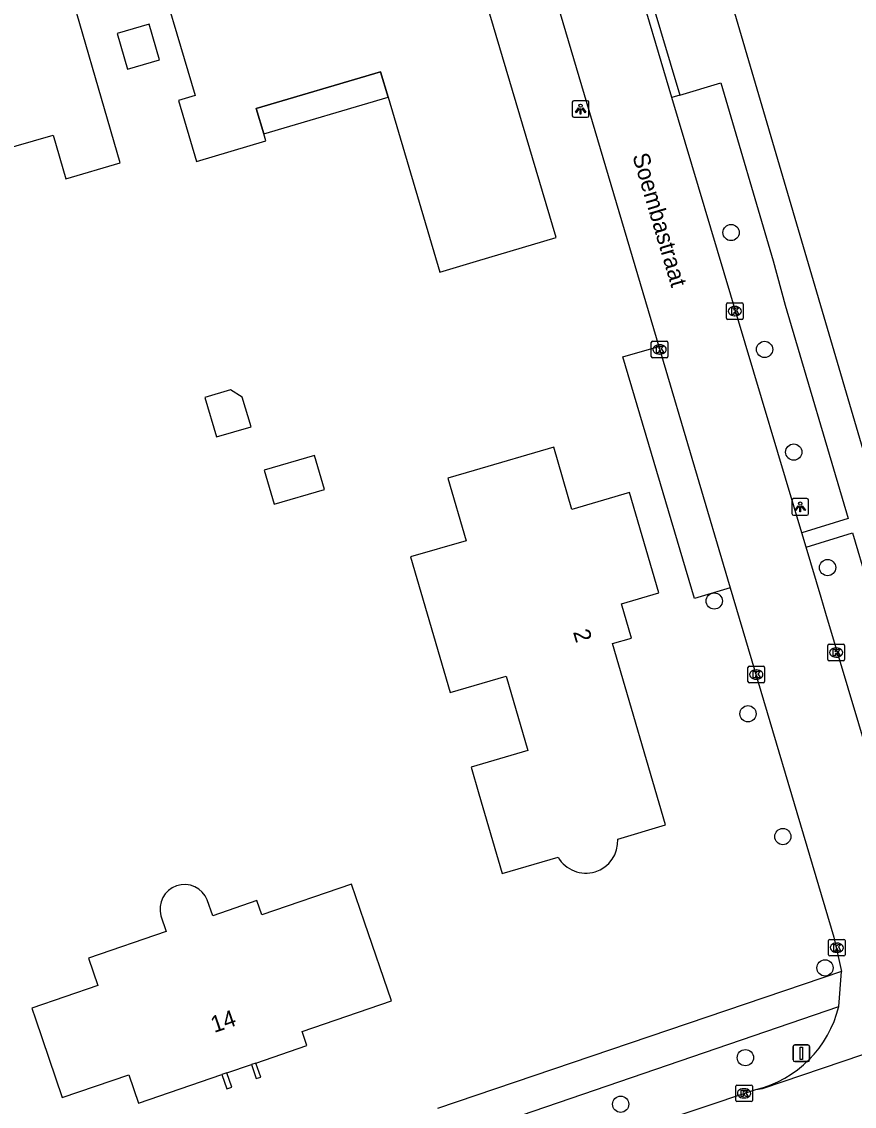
# Model space of a CAD drawing. Extents: x 162417 to 163721, y 384268 to 385416.
# Drawn here: x 163274.6 to 163324.7, y 384590.7 to 384656 of the extents above; entities that cross this region are included whole.
import ezdxf

# ---------------------------------------------------------------- set-up
doc = ezdxf.new("R2010")
doc.units = 0
for name, color, linetype in [('IMGEO_Boom', 7, 'Continuous'), ('IMGEO_Kolk', 7, 'Continuous'), ('IMGEO_Lichtpunt', 7, 'Continuous'), ('IMGEO_Muur', 7, 'Continuous'), ('IMGEO_Openbare_ruimte_label', 7, 'Continuous'), ('IMGEO_Pand', 7, 'Continuous'), ('IMGEO_Pand_nummerreeks', 7, 'Continuous'), ('IMGEO_Pand_overbouw', 7, 'Continuous'), ('IMGEO_Rijbaan_lokaal_open', 7, 'Continuous'), ('IMGEO_Verkeersbordpaal', 7, 'Continuous'), ('IMGEO_Voetpad_open', 7, 'Continuous')]:
    doc.layers.add(name, color=color, linetype=linetype)

msp = doc.modelspace()

# ---------------------------------------------------------------- linework, layer by layer
at = {"layer": 'IMGEO_Boom'}
for centre in [(163317.284, 384643.273), (163319.297, 384636.239), (163321.054, 384630.059), (163323.09, 384623.109), (163316.269, 384621.1), (163318.299, 384614.313), (163320.398, 384606.923), (163322.938, 384599.019), (163318.144, 384593.615), (163310.637, 384590.813)]:
    msp.add_circle(centre, 0.489, dxfattribs=at)
at = {"layer": 'IMGEO_Kolk'}
for p, q in [((163317.082, 384639.043), (163317.934, 384639.043)), ((163317.007, 384638.117), (163317.007, 384638.969)), ((163317.495, 384638.823), (163317.52, 384638.823)), ((163318.008, 384638.969), (163318.008, 384638.117)), ((163317.934, 384638.043), (163317.082, 384638.043)), ((163317.518, 384638.263), (163317.493, 384638.263)), ((163312.48, 384635.812), (163312.48, 384636.664)), ((163312.555, 384636.738), (163313.407, 384636.738)), ((163312.968, 384636.518), (163312.993, 384636.518)), ((163313.481, 384636.664), (163313.481, 384635.812)), ((163312.991, 384635.958), (163312.966, 384635.958)), ((163313.407, 384635.738), (163312.555, 384635.738)), ((163323.107, 384617.572), (163323.107, 384618.424)), ((163323.182, 384618.498), (163324.034, 384618.498)), ((163323.595, 384618.278), (163323.62, 384618.278)), ((163324.108, 384618.424), (163324.108, 384617.572)), ((163323.618, 384617.718), (163323.593, 384617.718)), ((163318.298, 384616.244), (163318.298, 384617.096)), ((163318.373, 384617.17), (163319.225, 384617.17)), ((163318.786, 384616.95), (163318.811, 384616.95)), ((163319.299, 384617.096), (163319.299, 384616.244)), ((163324.034, 384617.498), (163323.182, 384617.498)), ((163318.809, 384616.39), (163318.784, 384616.39)), ((163319.225, 384616.17), (163318.373, 384616.17)), ((163323.148, 384599.809), (163323.148, 384600.661)), ((163323.223, 384600.735), (163324.075, 384600.735)), ((163324.149, 384600.661), (163324.149, 384599.809)), ((163323.659, 384599.955), (163323.634, 384599.955)), ((163323.636, 384600.515), (163323.661, 384600.515)), ((163324.075, 384599.735), (163323.223, 384599.735)), ((163317.563, 384591.043), (163317.563, 384591.895)), ((163317.638, 384591.969), (163318.49, 384591.969)), ((163318.051, 384591.749), (163318.076, 384591.749)), ((163318.564, 384591.895), (163318.564, 384591.043)), ((163318.49, 384590.969), (163317.638, 384590.969)), ((163318.074, 384591.189), (163318.049, 384591.189))]:
    msp.add_line(p, q, dxfattribs=at)
for points in [[(163317.082, 384639.043), (163317.934, 384639.043)], [(163317.007, 384638.117), (163317.007, 384638.969)], [(163317.328, 384638.743), (163317.451, 384638.743), (163317.451, 384638.592), (163317.581, 384638.743), (163317.745, 384638.743), (163317.599, 384638.592), (163317.752, 384638.343), (163317.6, 384638.343), (163317.515, 384638.507), (163317.451, 384638.44), (163317.451, 384638.343), (163317.328, 384638.343), (163317.328, 384638.743)], [(163318.008, 384638.969), (163318.008, 384638.117)], [(163317.934, 384638.043), (163317.082, 384638.043)], [(163312.48, 384635.812), (163312.48, 384636.664)], [(163312.555, 384636.738), (163313.407, 384636.738)], [(163312.801, 384636.438), (163312.924, 384636.438), (163312.924, 384636.287), (163313.054, 384636.438), (163313.218, 384636.438), (163313.072, 384636.287), (163313.225, 384636.038), (163313.073, 384636.038), (163312.988, 384636.202), (163312.924, 384636.135), (163312.924, 384636.038), (163312.801, 384636.038), (163312.801, 384636.438)], [(163313.481, 384636.664), (163313.481, 384635.812)], [(163313.407, 384635.738), (163312.555, 384635.738)], [(163323.107, 384617.572), (163323.107, 384618.424)], [(163323.182, 384618.498), (163324.034, 384618.498)], [(163323.428, 384618.198), (163323.551, 384618.198), (163323.551, 384618.047), (163323.681, 384618.198), (163323.845, 384618.198), (163323.699, 384618.047), (163323.852, 384617.798), (163323.7, 384617.798), (163323.615, 384617.962), (163323.551, 384617.895), (163323.551, 384617.798), (163323.428, 384617.798), (163323.428, 384618.198)], [(163324.108, 384618.424), (163324.108, 384617.572)], [(163318.298, 384616.244), (163318.298, 384617.096)], [(163318.373, 384617.17), (163319.225, 384617.17)], [(163318.619, 384616.87), (163318.742, 384616.87), (163318.742, 384616.719), (163318.872, 384616.87), (163319.036, 384616.87), (163318.89, 384616.719), (163319.043, 384616.47), (163318.891, 384616.47), (163318.806, 384616.634), (163318.742, 384616.567), (163318.742, 384616.47), (163318.619, 384616.47), (163318.619, 384616.87)], [(163319.299, 384617.096), (163319.299, 384616.244)], [(163324.034, 384617.498), (163323.182, 384617.498)], [(163319.225, 384616.17), (163318.373, 384616.17)], [(163323.148, 384599.809), (163323.148, 384600.661)], [(163323.223, 384600.735), (163324.075, 384600.735)], [(163324.149, 384600.661), (163324.149, 384599.809)], [(163323.469, 384600.435), (163323.592, 384600.435), (163323.592, 384600.284), (163323.722, 384600.435), (163323.886, 384600.435), (163323.74, 384600.284), (163323.893, 384600.035), (163323.741, 384600.035), (163323.656, 384600.199), (163323.592, 384600.132), (163323.592, 384600.035), (163323.469, 384600.035), (163323.469, 384600.435)], [(163324.075, 384599.735), (163323.223, 384599.735)], [(163317.563, 384591.043), (163317.563, 384591.895)], [(163317.638, 384591.969), (163318.49, 384591.969)], [(163317.884, 384591.669), (163318.007, 384591.669), (163318.007, 384591.518), (163318.137, 384591.669), (163318.301, 384591.669), (163318.155, 384591.518), (163318.308, 384591.269), (163318.156, 384591.269), (163318.071, 384591.433), (163318.007, 384591.366), (163318.007, 384591.269), (163317.884, 384591.269), (163317.884, 384591.669)], [(163318.564, 384591.895), (163318.564, 384591.043)], [(163318.49, 384590.969), (163317.638, 384590.969)]]:
    msp.add_lwpolyline(points, dxfattribs=at)
for centre, start, end in [((163317.084, 384638.967), 91.55205, 178.44795), ((163317.084, 384638.967), 91.55205, 178.44795), ((163317.932, 384638.967), 1.55205, 88.44795), ((163317.932, 384638.967), 1.55205, 88.44795), ((163317.084, 384638.119), 181.55205, 268.44795), ((163317.084, 384638.119), 181.55205, 268.44795), ((163317.932, 384638.119), 271.55205, 358.44795), ((163317.932, 384638.119), 271.55205, 358.44795), ((163312.557, 384636.662), 91.55205, 178.44795), ((163312.557, 384636.662), 91.55205, 178.44795), ((163313.405, 384636.662), 1.55205, 88.44795), ((163313.405, 384636.662), 1.55205, 88.44795), ((163312.557, 384635.814), 181.55205, 268.44795), ((163312.557, 384635.814), 181.55205, 268.44795), ((163313.405, 384635.814), 271.55205, 358.44795), ((163313.405, 384635.814), 271.55205, 358.44795), ((163323.184, 384618.422), 91.55205, 178.44795), ((163323.184, 384618.422), 91.55205, 178.44795), ((163324.032, 384618.422), 1.55205, 88.44795), ((163324.032, 384618.422), 1.55205, 88.44795), ((163323.184, 384617.574), 181.55205, 268.44795), ((163323.184, 384617.574), 181.55205, 268.44795), ((163324.032, 384617.574), 271.55205, 358.44795), ((163324.032, 384617.574), 271.55205, 358.44795), ((163318.375, 384617.094), 91.55205, 178.44795), ((163318.375, 384617.094), 91.55205, 178.44795), ((163319.223, 384617.094), 1.55205, 88.44795), ((163319.223, 384617.094), 1.55205, 88.44795), ((163318.375, 384616.246), 181.55205, 268.44795), ((163318.375, 384616.246), 181.55205, 268.44795), ((163319.223, 384616.246), 271.55205, 358.44795), ((163319.223, 384616.246), 271.55205, 358.44795), ((163323.225, 384600.659), 91.55205, 178.44795), ((163323.225, 384600.659), 91.55205, 178.44795), ((163324.073, 384600.659), 1.55205, 88.44795), ((163324.073, 384600.659), 1.55205, 88.44795), ((163323.225, 384599.811), 181.55205, 268.44795), ((163323.225, 384599.811), 181.55205, 268.44795), ((163324.073, 384599.811), 271.55205, 358.44795), ((163324.073, 384599.811), 271.55205, 358.44795), ((163317.64, 384591.893), 91.55205, 178.44795), ((163317.64, 384591.893), 91.55205, 178.44795), ((163318.488, 384591.893), 1.55205, 88.44795), ((163318.488, 384591.893), 1.55205, 88.44795), ((163317.64, 384591.045), 181.55205, 268.44795), ((163317.64, 384591.045), 181.55205, 268.44795), ((163318.488, 384591.045), 271.55205, 358.44795), ((163318.488, 384591.045), 271.55205, 358.44795)]:
    msp.add_arc(centre, 0.0765, start, end, dxfattribs=at)
for centre, major_axis, ratio, start_param, end_param in [((163317.494, 384638.543), (-0.387, 0.002), 0.722429, 4.712389, 7.853982), ((163317.519, 384638.543), (-0.39, 0.002), 0.717154, 1.570796, 4.712389), ((163312.967, 384636.238), (-0.387, 0.002), 0.722429, 4.712389, 7.853982), ((163312.992, 384636.238), (-0.39, 0.002), 0.717154, 1.570796, 4.712389), ((163323.594, 384617.998), (-0.387, 0.002), 0.722429, 4.712389, 7.853982), ((163323.619, 384617.998), (-0.39, 0.002), 0.717154, 1.570796, 4.712389), ((163318.785, 384616.67), (-0.387, 0.002), 0.722429, 4.712389, 7.853982), ((163318.81, 384616.67), (-0.39, 0.002), 0.717154, 1.570796, 4.712389), ((163323.635, 384600.235), (-0.387, 0.002), 0.722429, 4.712389, 7.853982), ((163323.66, 384600.235), (-0.39, 0.002), 0.717154, 1.570796, 4.712389), ((163318.05, 384591.469), (-0.387, 0.002), 0.722429, 4.712389, 7.853982), ((163318.075, 384591.469), (-0.39, 0.002), 0.717154, 1.570796, 4.712389)]:
    msp.add_ellipse(centre, major_axis=major_axis, ratio=ratio, start_param=start_param, end_param=end_param, dxfattribs=at)
at = {"layer": 'IMGEO_Lichtpunt'}
for p, q in [((163307.725, 384651.11), (163307.725, 384650.303)), ((163307.725, 384651.11), (163307.725, 384650.303)), ((163308.627, 384651.205), (163307.819, 384651.205)), ((163308.627, 384651.205), (163307.819, 384651.205)), ((163308.721, 384650.303), (163308.721, 384651.11)), ((163308.721, 384650.303), (163308.721, 384651.11)), ((163307.819, 384650.209), (163308.627, 384650.209)), ((163307.819, 384650.209), (163308.627, 384650.209)), ((163320.944, 384627.165), (163320.944, 384626.358)), ((163320.944, 384627.165), (163320.944, 384626.358)), ((163321.846, 384627.26), (163321.038, 384627.26)), ((163321.846, 384627.26), (163321.038, 384627.26)), ((163321.94, 384626.358), (163321.94, 384627.165)), ((163321.94, 384626.358), (163321.94, 384627.165)), ((163321.038, 384626.264), (163321.846, 384626.264)), ((163321.038, 384626.264), (163321.846, 384626.264))]:
    msp.add_line(p, q, dxfattribs=at)
for points in [[(163308.099, 384650.774), (163308.138, 384650.746), (163307.95, 384650.484), (163307.912, 384650.511), (163308.099, 384650.774)], [(163308.201, 384650.726), (163308.248, 384650.726), (163308.248, 384650.404), (163308.201, 384650.404), (163308.201, 384650.726)], [(163308.311, 384650.746), (163308.349, 384650.773), (163308.536, 384650.511), (163308.497, 384650.483), (163308.311, 384650.746)], [(163321.318, 384626.829), (163321.357, 384626.801), (163321.169, 384626.539), (163321.131, 384626.566), (163321.318, 384626.829)], [(163321.42, 384626.781), (163321.467, 384626.781), (163321.467, 384626.459), (163321.42, 384626.459), (163321.42, 384626.781)], [(163321.53, 384626.801), (163321.568, 384626.828), (163321.755, 384626.566), (163321.716, 384626.538), (163321.53, 384626.801)]]:
    msp.add_lwpolyline(points, dxfattribs=at)
for centre in [(163308.224, 384650.908), (163321.443, 384626.963)]:
    msp.add_circle(centre, 0.0994, dxfattribs=at)
for centre, start, end in [((163307.819, 384651.11), 90, 180), ((163307.819, 384651.11), 90, 180), ((163308.627, 384651.11), 0, 90), ((163308.627, 384651.11), 0, 90), ((163307.819, 384650.303), 180, 270), ((163307.819, 384650.303), 180, 270), ((163308.627, 384650.303), 270, 0), ((163308.627, 384650.303), 270, 360), ((163321.038, 384627.165), 90, 180), ((163321.038, 384627.165), 90, 180), ((163321.846, 384627.165), 0, 90), ((163321.846, 384627.165), 0, 90), ((163321.038, 384626.358), 180, 270), ((163321.038, 384626.358), 180, 270), ((163321.846, 384626.358), 270, 0), ((163321.846, 384626.358), 270, 360)]:
    msp.add_arc(centre, 0.0946, start, end, dxfattribs=at)
at = {"layer": 'IMGEO_Muur'}
for points in [[(163288.413, 384593.203), (163288.701, 384592.358), (163288.968, 384592.449), (163288.681, 384593.289)], [(163286.632, 384592.601), (163286.924, 384591.745), (163287.23, 384591.849), (163286.939, 384592.699)]]:
    msp.add_lwpolyline(points, dxfattribs=at)
at = {"layer": 'IMGEO_Pand'}
for points in [[(163288.704, 384650.731), (163296.183, 384652.945), (163296.634, 384651.421), (163299.749, 384640.897), (163301.95, 384641.549), (163306.744, 384642.968), (163299.758, 384666.57), (163292.855, 384664.526), (163293.012, 384663.999), (163289.195, 384662.869), (163288.469, 384665.32), (163287.845, 384667.428), (163280.899, 384665.449), (163282.318, 384660.655), (163285.022, 384651.517), (163284.023, 384651.221), (163285.109, 384647.551), (163289.279, 384648.786), (163289.155, 384649.207), (163288.704, 384650.731)], [(163260.25, 384660.667), (163264.482, 384645.818), (163264.607, 384645.854), (163264.63, 384645.772), (163270.801, 384647.562), (163270.819, 384647.5), (163276.473, 384649.14), (163277.235, 384646.514), (163280.51, 384647.464), (163276.954, 384659.724), (163274.19, 384658.922), (163274.054, 384659.406), (163270.078, 384658.288), (163268.6, 384663.42)], [(163280.322, 384655.244), (163280.957, 384653.097), (163282.882, 384653.667), (163282.247, 384655.814), (163280.322, 384655.244)], [(163285.605, 384633.351), (163286.301, 384630.973), (163288.384, 384631.583), (163287.861, 384633.367), (163287.148, 384633.802), (163285.605, 384633.351)], [(163310.459, 384606.772), (163313.338, 384607.635), (163310.149, 384618.533), (163311.289, 384618.866), (163310.686, 384620.926), (163312.938, 384621.584), (163311.169, 384627.628), (163307.704, 384626.614), (163306.609, 384630.357), (163301.811, 384628.953), (163300.227, 384628.489), (163301.329, 384624.726), (163297.984, 384623.747), (163300.372, 384615.59), (163303.745, 384616.578), (163305.054, 384612.106), (163301.635, 384611.105), (163302.104, 384609.503), (163303.509, 384604.704), (163306.872, 384605.673)], [(163289.17, 384628.974), (163289.77, 384626.922), (163292.8, 384627.809), (163292.199, 384629.861), (163289.17, 384628.974)], [(163288.681, 384593.289), (163291.754, 384594.339), (163291.46, 384595.2), (163296.839, 384597.038), (163295.222, 384601.77), (163294.44, 384604.058), (163289.033, 384602.211), (163288.74, 384603.068), (163286.077, 384602.159), (163285.753, 384603.107)], [(163282.96, 384602.156), (163283.282, 384601.213), (163278.596, 384599.612), (163279.16, 384597.963), (163275.182, 384596.604), (163275.408, 384595.943), (163277.025, 384591.211), (163281.032, 384592.58), (163281.611, 384590.885), (163286.632, 384592.601)], [(163286.939, 384592.699), (163288.413, 384593.203)], [(163288.681, 384593.289), (163288.413, 384593.203)], [(163286.939, 384592.699), (163286.632, 384592.601)]]:
    msp.add_lwpolyline(points, dxfattribs=at)
for centre, radius, start, end in [((163308.535, 384606.648), 1.928, 210.38958, 3.67889), ((163284.381, 384602.56), 1.477, 21.75073, 195.85608)]:
    msp.add_arc(centre, radius, start, end, dxfattribs=at)
at = {"layer": 'IMGEO_Pand_overbouw'}
msp.add_lwpolyline([(163296.634, 384651.421), (163296.183, 384652.945), (163288.704, 384650.731), (163289.155, 384649.207)], close=True, dxfattribs=at)
at = {"layer": 'IMGEO_Rijbaan_lokaal_open'}
for points in [[(163300.352, 384678.47), (163300.634, 384677.935), (163312.926, 384636.415)], [(163313.725, 384651.399), (163311.404, 384659.211)], [(163321.537, 384625.199), (163317.662, 384638.152), (163313.725, 384651.399)], [(163312.926, 384636.415), (163317.237, 384621.888)], [(163321.795, 384624.338), (163321.537, 384625.199)], [(163329.005, 384600.235), (163322.986, 384620.355), (163322.7, 384621.313), (163321.795, 384624.338)], [(163317.237, 384621.888), (163323.475, 384600.863), (163323.936, 384598.792)], [(163323.763, 384596.699), (163323.936, 384598.792)], [(163318.779, 384591.691), (163319.165, 384591.77), (163336.053, 384597.486), (163336.48, 384597.749)], [(163301.239, 384585.814), (163318.779, 384591.691)]]:
    msp.add_lwpolyline(points, dxfattribs=at)
msp.add_arc((163317.157, 384598.289), 6.794, 283.80806, 346.46718, dxfattribs=at)
at = {"layer": 'IMGEO_Verkeersbordpaal'}
for p, q in [((163321.013, 384593.481), (163321.013, 384594.281)), ((163321.013, 384594.281), (163321.013, 384593.481)), ((163321.113, 384594.381), (163321.903, 384594.381)), ((163321.903, 384594.381), (163321.113, 384594.381)), ((163322.003, 384594.281), (163322.003, 384593.481)), ((163322.003, 384593.481), (163322.003, 384594.281)), ((163321.903, 384593.381), (163321.113, 384593.381)), ((163321.113, 384593.381), (163321.903, 384593.381))]:
    msp.add_line(p, q, dxfattribs=at)
msp.add_lwpolyline([(163321.433, 384594.256), (163321.583, 384594.256), (163321.583, 384593.506), (163321.433, 384593.506), (163321.433, 384594.256)], dxfattribs=at)
for centre, start, end in [((163321.113, 384594.281), 90, 180), ((163321.113, 384594.281), 90, 180), ((163321.903, 384594.281), 0, 90), ((163321.903, 384594.281), 360, 90), ((163321.113, 384593.481), 180, 270), ((163321.113, 384593.481), 180, 270), ((163321.903, 384593.481), 270, 0), ((163321.903, 384593.481), 270, 0)]:
    msp.add_arc(centre, 0.1, start, end, dxfattribs=at)
at = {"layer": 'IMGEO_Voetpad_open'}
for points in [[(163333.508, 384602.071), (163310.09, 384681.76), (163309.903, 384682.414)], [(163311.865, 384659.348), (163314.204, 384651.541)], [(163314.204, 384651.541), (163316.675, 384652.273), (163319.815, 384641.564), (163320.535, 384638.911), (163324.332, 384626.062), (163321.537, 384625.199)], [(163314.204, 384651.541), (163313.725, 384651.399)], [(163317.237, 384621.888), (163315.089, 384621.253), (163310.764, 384635.802), (163312.926, 384636.415)], [(163321.795, 384624.338), (163324.587, 384625.199), (163325.485, 384622.16), (163325.769, 384621.2), (163331.704, 384601.119)], [(163323.936, 384598.792), (163299.601, 384590.557)], [(163300.28, 384588.65), (163323.763, 384596.699)]]:
    msp.add_lwpolyline(points, dxfattribs=at)

# ---------------------------------------------------------------- texts
at = {"layer": 'IMGEO_Openbare_ruimte_label'}
msp.add_text('Soembastraat', height=1, rotation=286.55114, dxfattribs=at).set_placement((163311.329, 384647.895))
at = {"layer": 'IMGEO_Pand_nummerreeks'}
for s, rotation, p in [('2', 286.31573, (163307.762, 384619.24)), ('14', 18.87896, (163286.165, 384595.097))]:
    msp.add_text(s, height=1, rotation=rotation, dxfattribs=at).set_placement(p)

doc.saveas('drawing.dxf')
